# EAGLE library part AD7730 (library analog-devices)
Bridge Transducer ADC Source: http://www.analog.com/static/imported-files/data_sheets/AD7730_7730L.pdf
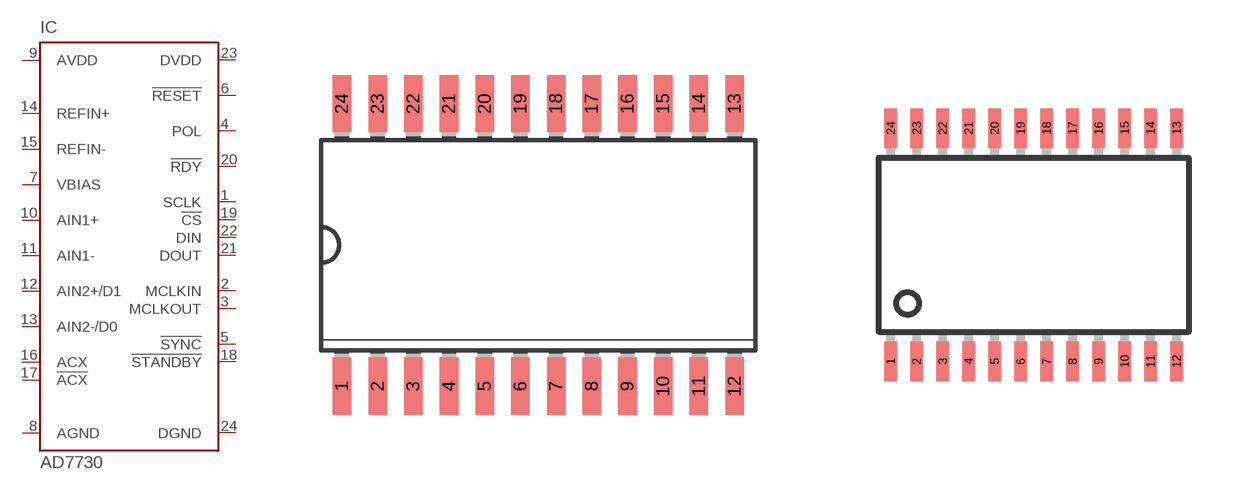
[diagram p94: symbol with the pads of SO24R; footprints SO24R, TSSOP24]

Designator prefix IC

## AD7730R (MF: ALTERA CORPORATION; MPN: AD7730LBRZ; OC_FARNELL: 1079295; OC_NEWARK: 59K5383)  [SO24R]
1  SCLK  in
2  MCLKIN  in
3  MCLKOUT  out
4  POL  in
5  !SYNC  in
6  !RESET  in
7  VBIAS  pas
8  AGND  in
9  AVDD  in
10  AIN1+  in
11  AIN1-  in
12  AIN2+/D1
13  AIN2-/D0
14  REFIN+  in
15  REFIN-  in
16  ACX  out
17  !ACX  out
18  !STANDBY  in
19  !CS  in
20  !RDY  out
21  DOUT  out
22  DIN  in
23  DVDD  in
24  DGND  in

## AD7730RU (MF: ALTERA CORPORATION; MPN: AD7730BRUZ; OC_FARNELL: 1423932; OC_NEWARK: 59K5374)  [TSSOP24]
Pads as for SO24R

## AD7730N (MF: ALTERA CORPORATION; MPN: AD7730BN; OC_FARNELL: 9605487; OC_NEWARK: 48F1987)  [DIL24-3]
Pads as for SO24R

## Footprint SO24R (pad centres in mm)
24-Lead Wide Body SOIC (R-24) Source: http://www.analog.com/UploadedFiles/Data_Sheets/39677768AD7714_c.pdf
smd 0.66 x 2.032: 1 -6.985,-5.029; 2 -5.715,-5.029; 3 -4.445,-5.029; 4 -3.175,-5.029; 5 -1.905,-5.029; 6 -0.635,-5.029; 7 0.635,-5.029; 8 1.905,-5.029; 9 3.175,-5.029; 10 4.445,-5.029; 11 5.715,-5.029; 12 6.985,-5.029; 13 6.985,5.029; 14 5.715,5.029; 15 4.445,5.029; 16 3.175,5.029; 17 1.905,5.029; 18 0.635,5.029; 19 -0.635,5.029; 20 -1.905,5.029; 21 -3.175,5.029; 22 -4.445,5.029; 23 -5.715,5.029; 24 -6.985,5.029

## Footprint TSSOP24 (pad centres in mm)
24-Lead Thin Shrink Small Outline Package TSSOP (RU-24) Source: http://www.analog.com/UploadedFiles/Data_Sheets/39677768AD7714_c.pdf
smd 0.305 x 0.991: 1 -3.575,-2.918; 2 -2.925,-2.918; 3 -2.275,-2.918; 4 -1.625,-2.918; 5 -0.975,-2.918; 6 -0.325,-2.918; 7 0.325,-2.918; 8 0.975,-2.918; 9 1.625,-2.918; 10 2.275,-2.918; 11 2.925,-2.918; 12 3.575,-2.918; 13 3.575,2.918; 14 2.925,2.918; 15 2.275,2.918; 16 1.625,2.918; 17 0.975,2.918; 18 0.325,2.918; 19 -0.325,2.918; 20 -0.975,2.918; 21 -1.625,2.918; 22 -2.275,2.918; 23 -2.925,2.918; 24 -3.575,2.918

## Footprint DIL24-3 (pad centres in mm)
Dual In Line Package 0.3 inch
drill 0.813 long: 1 -13.97,-3.81; 2 -11.43,-3.81; 3 -8.89,-3.81; 4 -6.35,-3.81; 5 -3.81,-3.81; 6 -1.27,-3.81; 7 1.27,-3.81; 8 3.81,-3.81; 9 6.35,-3.81; 10 8.89,-3.81; 11 11.43,-3.81; 12 13.97,-3.81; 13 13.97,3.81; 14 11.43,3.81; 15 8.89,3.81; 16 6.35,3.81; 17 3.81,3.81; 18 1.27,3.81; 19 -1.27,3.81; 20 -3.81,3.81; 21 -6.35,3.81; 22 -8.89,3.81; 23 -11.43,3.81; 24 -13.97,3.81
